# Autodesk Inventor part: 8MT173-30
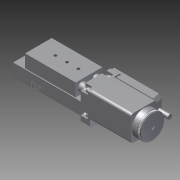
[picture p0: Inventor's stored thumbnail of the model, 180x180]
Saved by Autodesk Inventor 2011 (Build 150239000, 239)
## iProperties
Created: 2011-07
Part Number: 8MT173-30
Document SubType Name: Modeling
Designer: vadybininkas6
Density: 1 g/cm^3
Author: vadybininkas6
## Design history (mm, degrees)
feature "Base1"
body "Solid1"
